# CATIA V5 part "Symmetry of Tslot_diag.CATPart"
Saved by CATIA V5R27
Part number: Symmetry of Tslot_diag
Bounding box of the stored display mesh (mm): x -19.056 to 19.056, y -19.056 to 19.056, z -1318.68 to -638
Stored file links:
  \\triton.meca.polymtl.ca\usagers\zaoue\profiles\Desktop\varm_ass\structure prismatique\Symmetry of Tslot_diag.CATPart
  \\triton.meca.polymtl.ca\usagers\zaoue\profiles\Desktop\varm_ass\structure prismatique\Tslot_diag.CATPart
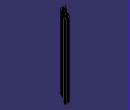
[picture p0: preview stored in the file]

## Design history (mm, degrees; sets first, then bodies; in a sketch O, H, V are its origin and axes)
Body1 (main body)
Body2 "Boss-Extrude1"
  Solid1: linked copy from another document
